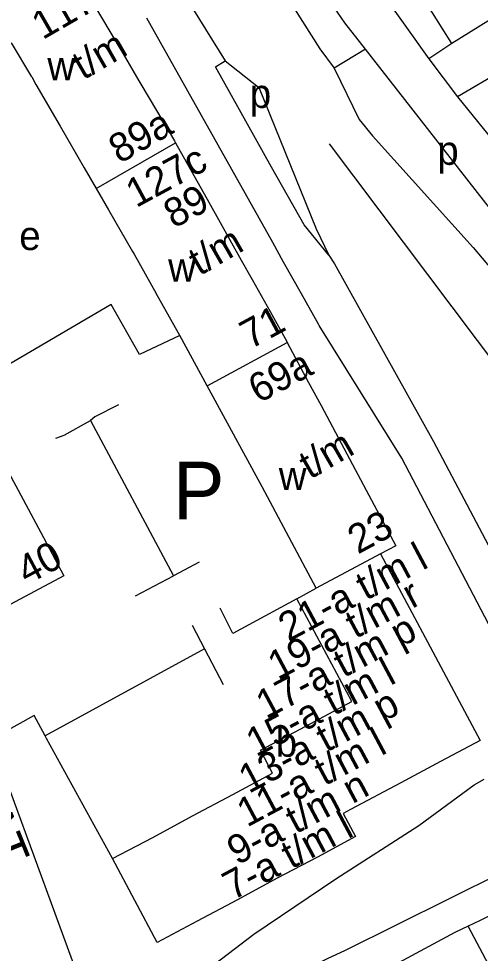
# Model space of a CAD drawing. Extents: x 159902 to 161769, y 383692 to 384875.
# Drawn here: x 160786.3 to 160850.4, y 383903 to 384032.8 of the extents above; entities that cross this region are included whole.
import ezdxf

# ---------------------------------------------------------------- set-up
doc = ezdxf.new("R2010")
doc.units = 0
for name, color, linetype in [('BLT_Basislijn', 7, 'Continuous'), ('BLT_Bebouwing', 7, 'Continuous'), ('BLT_Centroide', 7, 'Continuous'), ('BLT_Huisnummer_reeks', 7, 'Continuous'), ('BLT_Onderverdeling_panden', 7, 'Continuous'), ('BLT_Straatnaam', 7, 'Continuous'), ('BLT_Tekst_parkeren', 7, 'Continuous')]:
    doc.layers.add(name, color=color, linetype=linetype)

msp = doc.modelspace()

# ---------------------------------------------------------------- linework, layer by layer
at = {"layer": 'BLT_Basislijn'}
for p, q in [((160808.87, 384036.72), (160814.97, 384026.91)), ((160846.42, 384029.31), (160843.23, 384027.18)), ((160834.44, 384028.55), (160830.1, 384025.91)), ((160814.97, 384026.91), (160819.61, 384023.27)), ((160843.23, 384027.18), (160847.23, 384021.92)), ((160856.3, 384027.25), (160847.23, 384021.92)), ((160830.1, 384025.91), (160833.56, 384018.76)), ((160847.23, 384021.92), (160862.02, 384003.65)), ((160854.8, 383981.68), (160829.47, 384015.38)), ((160796.24, 383976.97), (160807.77, 383955.44)), ((160811.35, 383957.33), (160807.77, 383955.44)), ((160802.52, 383952.67), (160807.77, 383955.44)), ((160824.93, 383952.25), (160816.02, 383947.4)), ((160816.02, 383947.4), (160814.25, 383950.94)), ((160810.37, 383948.56), (160812.1, 383945.27)), ((160812.1, 383945.27), (160789.94, 383933.21)), ((160812.1, 383945.27), (160814.69, 383940.36)), ((160831.58, 383903.43), (160862.26, 383918.66))]:
    msp.add_line(p, q, dxfattribs=at)
for points in [[(160816.82, 384066.02), (160823.61, 384055.31), (160829.46, 384046.58), (160843.23, 384027.18)], [(160834.44, 384028.55), (160831.59, 384032.19), (160825.97, 384040.38)], [(160822.09, 384038.14), (160828.12, 384028.57), (160830.1, 384025.91)], [(160828.01, 383990.17), (160827.91, 383990.36), (160825.55, 383994.56), (160823.08, 383998.99), (160821.56, 384001.7), (160804.07, 384032.85)], [(160859.4, 383989.14), (160858.09, 383996.88), (160856.29, 384000.6), (160834.44, 384028.55)], [(160829.35, 383999.96), (160825.93, 384004.14), (160821.41, 384012.18), (160813.6, 384026.09), (160814.97, 384026.91)], [(160819.61, 384023.27), (160819.69, 384023.12), (160827.6, 384003.59), (160829.35, 383999.96)], [(160833.56, 384018.76), (160835.44, 384016.53), (160849.38, 384000.99), (160859.4, 383989.14)], [(160829.35, 383999.96), (160830.12, 383998.74), (160843.91, 383974.06), (160853.63, 383955.72)], [(160808.64, 383988.77), (160803.06, 383986.17), (160799.11, 383993.1), (160778.79, 383981.22)], [(160855.76, 383940.73), (160839.47, 383971.76), (160828.01, 383990.17)], [(160800.16, 383979.15), (160796.87, 383977.51), (160796.24, 383976.97)], [(160791.46, 383974.53), (160792.6, 383974.97), (160796.24, 383976.97)], [(160789.94, 383933.21), (160788.45, 383936.02), (160783.16, 383933.13), (160782.49, 383932.48), (160794.23, 383900.62), (160795.68, 383898.07), (160797.42, 383896), (160797.84, 383895.65), (160800.29, 383894.78), (160802.93, 383894.69), (160805.42, 383895.54), (160806.44, 383896.13), (160818.93, 383905.69), (160830.31, 383913.34), (160841.85, 383920.77), (160849.53, 383926.4), (160850.93, 383927.2)], [(160799.33, 383916.16), (160790.14, 383932.84), (160789.94, 383933.21)], [(160860.84, 383911.54), (160854.02, 383909.42), (160850.26, 383907.54), (160848.7, 383906.79)], [(160809.3, 383753.02), (160834.49, 383785.31), (160836.4, 383788.02), (160867.15, 383826.48), (160870.9, 383862.33), (160862.47, 383878.6), (160857.32, 383890.56), (160848.7, 383906.79)], [(160848.7, 383906.79), (160846.85, 383905.9), (160826.29, 383894.85)], [(160812.43, 383892.03), (160814.7, 383893.7), (160817.02, 383895.31), (160819.39, 383896.86), (160821.8, 383898.33), (160824.25, 383899.74), (160826.74, 383901.08), (160829.26, 383902.34), (160831.58, 383903.43)]]:
    msp.add_lwpolyline(points, dxfattribs=at)
at = {"layer": 'BLT_Bebouwing'}
for p, q in [((160846.42, 384029.31), (160821.66, 384069.04)), ((160788.09, 384024.69), (160785.28, 384029.42)), ((160788.09, 384024.69), (160788.68, 384023.65)), ((160788.68, 384023.65), (160792.04, 384017.85)), ((160792.04, 384017.85), (160795.39, 384012.05)), ((160795.39, 384012.05), (160797.02, 384009.2)), ((160797.02, 384009.2), (160798.74, 384006.25)), ((160798.74, 384006.25), (160802.09, 384000.45)), ((160805.56, 383994.29), (160805.38, 383994.62)), ((160808.64, 383988.77), (160805.56, 383994.29)), ((160812.47, 383981.81), (160808.64, 383988.77)), ((160784.87, 383969.82), (160786.9, 383966.03)), ((160786.9, 383966.03), (160789.72, 383960.73)), ((160836.54, 383958.48), (160844.18, 383944.19)), ((160824.93, 383952.25), (160827.6, 383953.71)), ((160832.55, 383937.98), (160824.93, 383952.25)), ((160826.17, 383934.57), (160832.55, 383937.98)), ((160844.87, 383929.64), (160839.36, 383926.7)), ((160816, 383925.05), (160821.55, 383928.02)), ((160839.36, 383926.7), (160832.37, 383922.97)), ((160810.44, 383922.09), (160816, 383925.05)), ((160804.89, 383919.12), (160810.44, 383922.09)), ((160799.33, 383916.16), (160804.89, 383919.12)), ((160827.76, 383916.39), (160822.2, 383913.43)), ((160822.2, 383913.43), (160816.65, 383910.46)), ((160816.65, 383910.46), (160811.09, 383907.5))]:
    msp.add_line(p, q, dxfattribs=at)
for points in [[(160865.02, 384046.23), (160858.53, 384042.19), (160860.9, 384038.39), (160856.82, 384035.82), (160846.42, 384029.31)], [(160791.72, 384043.19), (160792.47, 384041.95), (160794.94, 384037.76), (160796.77, 384034.67), (160798.95, 384030.98), (160800.77, 384027.89), (160802.98, 384024.16), (160804.56, 384021.49), (160807.9, 384015.81), (160808.06, 384015.52)], [(160808.06, 384015.52), (160812.69, 384007.29), (160817.2, 383999.25), (160818.71, 383996.55), (160821.19, 383992.12), (160823.52, 383987.97), (160823.59, 383987.83)], [(160802.09, 384000.45), (160802.3, 384000.08), (160805.38, 383994.62)], [(160823.59, 383987.83), (160826.55, 383982.27), (160828.27, 383979.08), (160832.64, 383970.9), (160838.66, 383959.61), (160836.54, 383958.48)], [(160827.6, 383953.71), (160820.1, 383967.79), (160812.47, 383981.81)], [(160789.72, 383960.73), (160792.55, 383955.44), (160780.96, 383949.26)], [(160844.18, 383944.19), (160850.38, 383932.57), (160844.87, 383929.64)], [(160821.55, 383928.02), (160819.86, 383931.2), (160826.17, 383934.57)], [(160832.37, 383922.97), (160831.34, 383922.43), (160833.05, 383919.22), (160827.76, 383916.39)], [(160811.09, 383907.5), (160805.53, 383904.53), (160799.33, 383916.16)]]:
    msp.add_lwpolyline(points, dxfattribs=at)
at = {"layer": 'BLT_Onderverdeling_panden'}
for p, q in [((160797.02, 384009.2), (160808.06, 384015.52)), ((160812.47, 383981.81), (160823.59, 383987.83)), ((160836.54, 383958.48), (160827.6, 383953.71))]:
    msp.add_line(p, q, dxfattribs=at)

# ---------------------------------------------------------------- texts
at = {"layer": 'BLT_Centroide'}
for s, p in [('w', (160790.27, 384024.23)), ('p', (160818.37, 384020.38)), ('p', (160844.41, 384012.48)), ('e', (160786.36, 384000.65)), ('w', (160807.04, 383996.28)), ('w', (160822.4, 383967.34)), ('b', (160821.98, 383930.31))]:
    msp.add_text(s, height=4, dxfattribs=at).set_placement(p)
at = {"layer": 'BLT_Huisnummer_reeks'}
for s, rotation, p in [('117a', 29.9301, (160789.61, 384029.78)), ('t/m', 29.9301, (160795.23, 384024.19)), ('89a', 29.9301, (160800.29, 384012.57)), ('127c', 28.3985, (160802.59, 384006.46)), ('89', 28.3985, (160807.83, 384003.59)), ('t/m', 29.9301, (160811.38, 383997)), ('71', 28.3985, (160818.43, 383986.82)), ('69a', 28.3985, (160819.6, 383979.3)), ('t/m', 29.9301, (160826.74, 383968.76)), ('23', 28.3985, (160833.39, 383958.37)), ('40', 28.0756, (160787.43, 383954.11)), ('21-a t/m l', 28.0518, (160823.74, 383946.21)), ('19-a t/m r', 28.0518, (160822.28, 383940.89)), ('17-a t/m p', 28.0518, (160820.64, 383935.48)), ('15-a t/m l', 28.0518, (160819.26, 383930.21)), ('13-a t/m p', 28.0518, (160818.23, 383925.13)), ('11-a t/m l', 28.0518, (160817.99, 383920.46)), ('9-a t/m n', 28.0518, (160816.62, 383915.19)), ('7-a t/m l', 28.0518, (160816, 383910.32))]:
    msp.add_text(s, height=4, rotation=rotation, dxfattribs=at).set_placement(p)
at = {"layer": 'BLT_Straatnaam'}
msp.add_text('ROSA MANUSSTRAAT', height=5, rotation=291.9943, dxfattribs=at).set_placement((160756.54, 383980.73))
at = {"layer": 'BLT_Tekst_parkeren'}
msp.add_text('P', height=8, dxfattribs=at).set_placement((160807.72, 383963.26))

doc.saveas('drawing.dxf')
